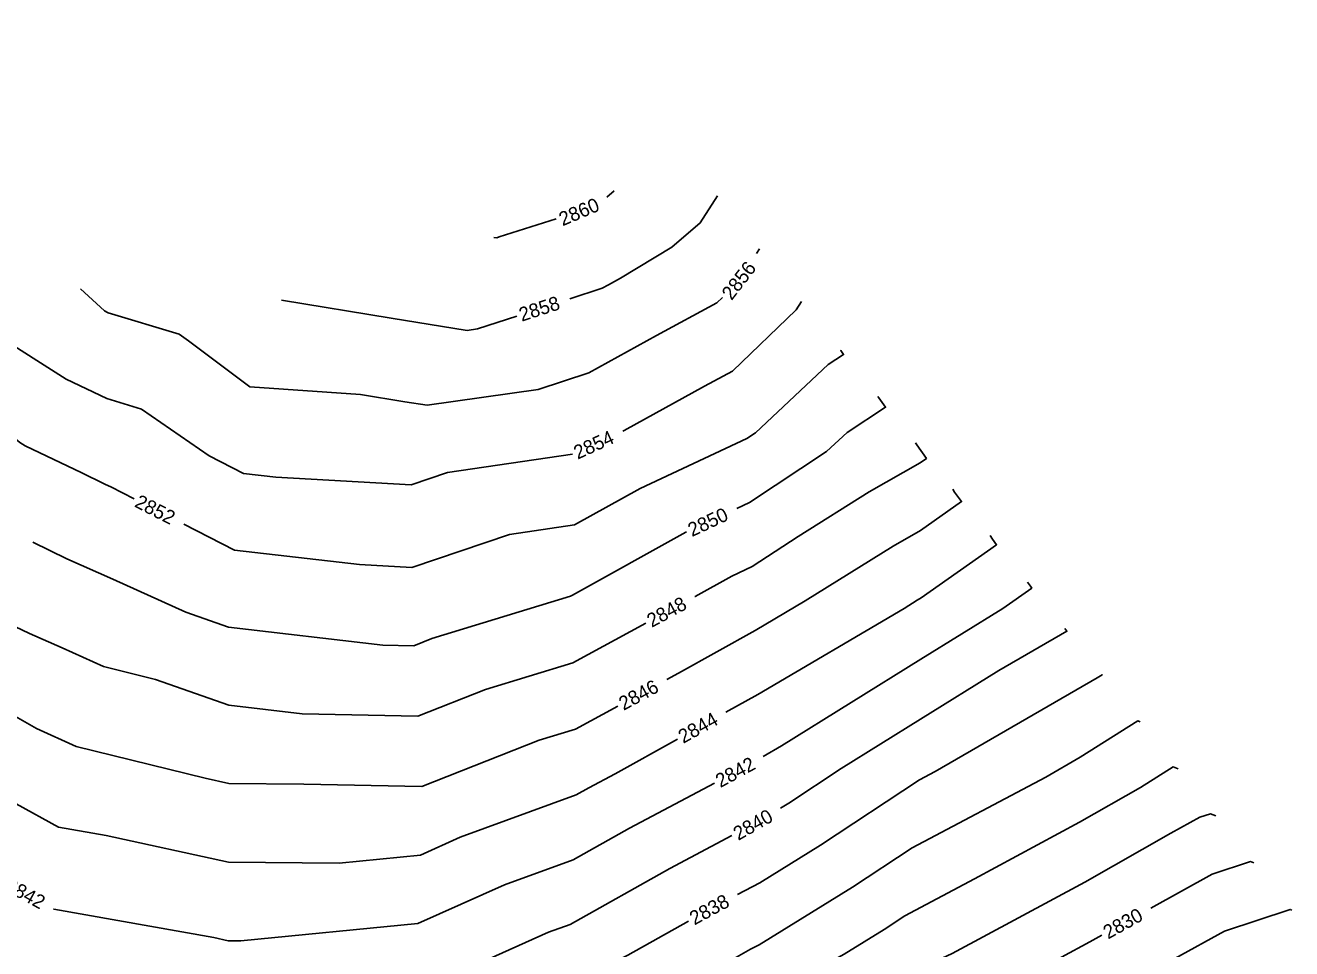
# Model space of a CAD drawing. Extents: x 1326424 to 1329294, y 1001359 to 1003823.
# Drawn here: x 1328837.1 to 1329018.9, y 1002390.5 to 1002523.1 of the extents above; entities that cross this region are included whole.
import ezdxf

# ---------------------------------------------------------------- set-up
doc = ezdxf.new("R2010")
doc.units = 0
doc.layers.add('Prop Rem of Exist Asph Pvmt', color=7, linetype='Continuous')
doc.layers.add('Scratch_Level_3', color=7, linetype='Continuous')

msp = doc.modelspace()

# ---------------------------------------------------------------- linework, layer by layer
at = {"layer": 'Prop Rem of Exist Asph Pvmt'}
for points in [[(1328920.6, 1002498.42), (1328921.64, 1002499.31)], [(1328904.39, 1002492.64), (1328904.8, 1002492.6), (1328905.13, 1002492.71), (1328913.33, 1002495.33)], [(1328945.51, 1002410.7), (1328946.7, 1002411.44), (1328954.22, 1002416.4), (1328965.63, 1002423.5), (1328976.85, 1002430.45), (1328986.63, 1002436.1), (1328986.34, 1002436.51)], [(1328844.07, 1002384.57), (1328845.56, 1002384.47), (1328863.29, 1002381.97), (1328866.95, 1002381.79), (1328890.34, 1002384.07), (1328892.32, 1002384.66), (1328893.72, 1002384.92), (1328895.25, 1002385.64), (1328902.31, 1002388.45), (1328912.24, 1002392.88), (1328915.34, 1002394.02), (1328929.63, 1002402.03), (1328938.55, 1002406.76)]]:
    msp.add_lwpolyline(points, dxfattribs=at)
at = {"layer": 'Scratch_Level_3'}
for points in [[(1328781.25, 1002523.09), (1328784.64, 1002518.47), (1328787.71, 1002513.8), (1328794.07, 1002506.19), (1328799.84, 1002498.89), (1328807.51, 1002490.36), (1328812.11, 1002485.67), (1328815.4, 1002481.93), (1328822.63, 1002474.36), (1328835.12, 1002464.18), (1328836.35, 1002463.18), (1328837.1, 1002462.7), (1328845.23, 1002458.82), (1328848.45, 1002457.26), (1328848.65, 1002457.17), (1328849.39, 1002456.83), (1328852.74, 1002455.12)], [(1328915.28, 1002483.84), (1328919.94, 1002485.36), (1328920.81, 1002485.84), (1328922.55, 1002486.78), (1328929.91, 1002491.23), (1328934, 1002494.73), (1328936.49, 1002498.59)], [(1328942.07, 1002490.31), (1328942.52, 1002491)], [(1328824.63, 1002486.33), (1328827.45, 1002483.12), (1328832.82, 1002478.76), (1328843.01, 1002472.27), (1328848.81, 1002469.5), (1328853.82, 1002468), (1328863.52, 1002461.27), (1328868.46, 1002458.75), (1328873.1, 1002458.21), (1328892.5, 1002457.13), (1328897.7, 1002458.9), (1328915.64, 1002461.52)], [(1328845.04, 1002485.28), (1328848.49, 1002482.12), (1328848.92, 1002481.84), (1328849.01, 1002481.8), (1328859.19, 1002478.74), (1328860.56, 1002477.79), (1328869.34, 1002471.21), (1328885.23, 1002470.1), (1328891.62, 1002469.05), (1328894.8, 1002468.54), (1328910.75, 1002470.83), (1328918.03, 1002473.21), (1328927.71, 1002478.56), (1328936.39, 1002483.26), (1328937.2, 1002484.03)], [(1328873.88, 1002483.61), (1328889.64, 1002481.03), (1328900.56, 1002479.29), (1328902.03, 1002479.5), (1328907.67, 1002481.35)], [(1328922.88, 1002464.82), (1328923.07, 1002464.91), (1328934.61, 1002471.28), (1328938.65, 1002473.46), (1328947.78, 1002482.22), (1328948.55, 1002483.42)], [(1328859.87, 1002451.48), (1328867.17, 1002447.75), (1328885.07, 1002445.67), (1328892.61, 1002445.25), (1328906.61, 1002450.01), (1328915.94, 1002451.38), (1328925.37, 1002456.61), (1328940.67, 1002463.75), (1328941.94, 1002464.6), (1328952.34, 1002474.38), (1328954.58, 1002475.83), (1328954.18, 1002476.39), (1328954.13, 1002476.46)], [(1328939.27, 1002453.73), (1328941.07, 1002454.57), (1328952.14, 1002461.89), (1328955.07, 1002464.65), (1328960.6, 1002468.25), (1328959.63, 1002469.62), (1328959.5, 1002469.8)], [(1328933.22, 1002441.07), (1328933.28, 1002441.1), (1328938.53, 1002444.02), (1328941.47, 1002445.39), (1328948.03, 1002449.72), (1328958.23, 1002456.1), (1328965.55, 1002460.28), (1328966.45, 1002460.91), (1328965.07, 1002462.86), (1328964.87, 1002463.14)], [(1328929.19, 1002429.17), (1328930.9, 1002430.09), (1328941.87, 1002436.22), (1328949.08, 1002440.46), (1328961.67, 1002448.33), (1328965.62, 1002450.58), (1328971.5, 1002454.71), (1328970.51, 1002456.09), (1328970.23, 1002456.49)], [(1328838.21, 1002448.88), (1328843.08, 1002446.52), (1328849.69, 1002443.6), (1328860.15, 1002438.86), (1328866.3, 1002436.68), (1328888.44, 1002434.11), (1328892.89, 1002434.02), (1328895.48, 1002435.05), (1328915.36, 1002441.12), (1328915.68, 1002441.29), (1328931.95, 1002450.31), (1328932.02, 1002450.35)], [(1328937.69, 1002424.49), (1328942.26, 1002427.04), (1328963.26, 1002439.39), (1328965.12, 1002440.55), (1328965.7, 1002440.88), (1328976.54, 1002448.51), (1328975.96, 1002449.33), (1328975.6, 1002449.83)], [(1328943.05, 1002418.11), (1328945.67, 1002419.65), (1328965.67, 1002432.09), (1328977.42, 1002439.37), (1328981.59, 1002442.3), (1328981.4, 1002442.56), (1328980.97, 1002443.17)], [(1328832.08, 1002439.6), (1328835.61, 1002436.79), (1328837.71, 1002435.78), (1328842.42, 1002433.7), (1328848.34, 1002431.04), (1328855.81, 1002429.19), (1328866.32, 1002425.48), (1328876.84, 1002424.26), (1328893.47, 1002423.92), (1328903.19, 1002427.76), (1328915.72, 1002431.59), (1328926.18, 1002437.26)], [(1328827.84, 1002429.25), (1328828.8, 1002428.47), (1328831.65, 1002426.16), (1328838.74, 1002422.12), (1328844.43, 1002419.57), (1328862.96, 1002414.99), (1328866.33, 1002414.26), (1328877.1, 1002414.16), (1328894.06, 1002413.82), (1328910.89, 1002420.48), (1328916.08, 1002422.06), (1328922.16, 1002425.35)], [(1328939.34, 1002398.31), (1328942.53, 1002400), (1328951.26, 1002405.39), (1328965.45, 1002414.75), (1328967.73, 1002415.95), (1328990.96, 1002429.4), (1328991.68, 1002429.86), (1328991.71, 1002429.84)], [(1328932.4, 1002385.84), (1328939.2, 1002389.31), (1328941.23, 1002390.44), (1328942.44, 1002391.09), (1328955.83, 1002399.34), (1328964.41, 1002405), (1328983.61, 1002415.17), (1328988.55, 1002418.03), (1328996.79, 1002423.24), (1328997.15, 1002423.09)], [(1328835.82, 1002411.33), (1328841.89, 1002407.97), (1328848.71, 1002406.77), (1328866.28, 1002402.97), (1328882.15, 1002402.82), (1328893.84, 1002403.96), (1328899.55, 1002406.52), (1328916.21, 1002412.6), (1328918.03, 1002413.63), (1328921.79, 1002415.62), (1328930.71, 1002420.6)], [(1328923.96, 1002373.32), (1328942.16, 1002383.1), (1328946.4, 1002385.21), (1328954.64, 1002389.74), (1328960.39, 1002393.29), (1328963.36, 1002395.25), (1328973.37, 1002400.55), (1328988.44, 1002408.69), (1328997.21, 1002413.66), (1329001.89, 1002416.62), (1329002.58, 1002416.34)], [(1328841.16, 1002396.22), (1328841.2, 1002396.19), (1328864.19, 1002392.12), (1328866.23, 1002391.68), (1328868.06, 1002391.66), (1328893.48, 1002394.15), (1328905.9, 1002399.7), (1328915.78, 1002403.31), (1328923.83, 1002407.83), (1328936.02, 1002414.29)], [(1328914.46, 1002360.68), (1328915.39, 1002361.12), (1328924.92, 1002366.27), (1328941.82, 1002375.35), (1328951.41, 1002380.14), (1328963.18, 1002386.61), (1328970.16, 1002389.83), (1328989.18, 1002400.1), (1329001.53, 1002407.1), (1329005.7, 1002409.4), (1329007.24, 1002409.91), (1329008.02, 1002409.59)], [(1328998.65, 1002396.36), (1329007.48, 1002401.23), (1329012.96, 1002403.04), (1329013.45, 1002402.84)], [(1328982.57, 1002379.96), (1328990.28, 1002383.39), (1329002.13, 1002389.13), (1329009.25, 1002393.06), (1329018.68, 1002396.17), (1329018.89, 1002396.08)], [(1328837.14, 1002375.26), (1328840.6, 1002373.97), (1328857.43, 1002372.85), (1328859.91, 1002372.5), (1328867.8, 1002372.12), (1328881.39, 1002373.44), (1328889.52, 1002375.87), (1328895.21, 1002376.9), (1328901.47, 1002379.87), (1328915.21, 1002385.32), (1328923.6, 1002389.6), (1328932.31, 1002394.49)], [(1328902.41, 1002347.48), (1328907.35, 1002349.7), (1328915.27, 1002353.44), (1328937.58, 1002365.5), (1328941.49, 1002367.6), (1328956.42, 1002375.06), (1328963.98, 1002379.21), (1328985.83, 1002389.3), (1328989.92, 1002391.51), (1328991.65, 1002392.49)]]:
    msp.add_lwpolyline(points, dxfattribs=at)

# ---------------------------------------------------------------- texts
at = {"layer": 'Prop Rem of Exist Asph Pvmt'}
for s, rotation, p in [('2860', 23.0443, (1328914.25, 1002494.23)), ('2840', 29.514, (1328939.46, 1002406))]:
    msp.add_text(s, height=2, rotation=rotation, dxfattribs=at).set_placement(p)
at = {"layer": 'Scratch_Level_3'}
for s, rotation, p in [('2856', 52.185, (1328938.5, 1002483.5)), ('2858', 18.1267, (1328908.38, 1002480.53)), ('2854', 24.4486, (1328916.41, 1002460.73)), ('2852', 332.9379, (1328852.66, 1002454.04)), ('2850', 25.0379, (1328932.82, 1002449.62)), ('2848', 28.4601, (1328927.03, 1002436.58)), ('2846', 28.4601, (1328923, 1002424.67)), ('2844', 29.1674, (1328931.56, 1002419.93)), ('2842', 28.4737, (1328936.88, 1002413.58)), ('2842', 331.0657, (1328834.04, 1002399.01)), ('2838', 28.5433, (1328933.16, 1002393.86)), ('2830', 28.9557, (1328992.53, 1002391.84))]:
    msp.add_text(s, height=2, rotation=rotation, dxfattribs=at).set_placement(p)

doc.saveas('drawing.dxf')
